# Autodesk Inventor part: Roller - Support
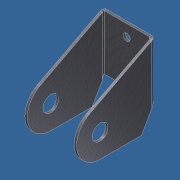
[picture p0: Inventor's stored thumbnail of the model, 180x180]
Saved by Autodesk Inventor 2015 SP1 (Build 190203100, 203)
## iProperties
Category: Mechanical Engineering Drawing and Design - CADD
Manager: Fábio Ricardo de Oliveira Souza
Company: SENAI - Serviço Nacional de Aprendizagem Industrial
Created: 2011-06
Part Number: Roller - Support
Material: Steel
Description: Steel - DIN-20CrMoS4
Document SubType Name: Sheet Metal
Designer: Guilherme Augusto Franco de Souza
Engineer: George Geraldo de Oliveia Silva
Authority: Fábio Ricardo de Oliveira Soza
Density: 7.85 g/cm^3
Flat Pattern Width: 5 cm
Flat Pattern Length: 12.8644 cm
Flat Pattern Area: 64.3221 cm^2
Sheet Metal Rule: Default_mm
Sheet Metal Width: 50,000 mm
Sheet Metal Length: 128,644 mm
Sheet Metal Area: 6432,212 mm^2
Mass: 50.3251 g
Surface Area: 91.6447 cm^2
Volume: 6.41083 cm^3
Appearance: Machined 02
Subject: WorldSkill 2011 - London, England
Author: Guilherme Augusto Franco de Souza
Revision Number: 00
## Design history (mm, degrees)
sketch "Sketch1"
  geometry: L1 (-16.5, -60)-(-16.5, 0); L2 (-16.5, 0)-(16.5, 0); L3 (16.5, 0)-(16.5, -60); 2 further points
  constraints: 6 end point, 2 parallel, 1 coincident, 1 midpoint, 1 perpendicular, 1 vertical
  dimensions: "d0" = 33 distance of L1.end L2.end; "d1" = 60 distance of L1.start L1.end
extrude_surface "ExtrusionSrf1" sketch "Sketch1" dims "d2" = 50, "d3" = 0
sketch "Sketch2"
  geometry: L1 (0, -10)-(-8.66, -25); L2 (0, 25)-(0, -25) reference; L3 (0, 25)-(-41.894, 3.322); L4 (-35, -25)-(-8.66, -25); A1 r 15 centre (-35, -10) between (-41.894, 3.322) and (-35, -25); 2 further points
  constraints: 6 end point, 2 point on circle, 2 tangent, 1 centre point, 1 midpoint, 1 perpendicular, 1 vertical alignment
  dimensions: "d4" = 30 deg angle of L2 L1; "d5" = 10 distance of point (0, 0) L1.start; "d6" = 35 distance from line of L2 A1.centre; "d7" = 25 distance from line of point (0, 0) L4; "d33" = 15 radius of A1
extrude_surface "ExtrusionSrf2" sketch "Sketch2" dims "d9" = 50, "d10" = 0
feature "Trim1"
feature "Trim2"
feature "Trim3"
fillet "Fillet1" dims "d11" = 2
thicken "Thicken1" dims "d12" = 1.5
hole "Hole1" diameter "d15" = 10; stored, may be unused: countersink angle "d19" = 90 deg, drill point angle "d21" = 118 deg; dims "d13" = 10, "d14" = 10, "d16" = 6, "d17" = 4, "d18" = 2, "d20" = 1.5 (= Thickness)
sketch "Sketch3"
  geometry: L1 (0, 0)-(29, 0) reference; L2 (14.5, 27.5)-(14.5, 7.5); 2 further points
  constraints: 2 end point, 1 midpoint, 1 vertical, 1 vertical alignment
  dimensions: "d22" = 20 distance of L2.start L2.end; "d35" = 7.5 distance from line of L1 L2.end
hole "Hole2" sketch "Sketch3" at (14.5, 27.5), (14.5, 7.5) diameter "d26" = 4.5; stored, may be unused: countersink angle "d30" = 90 deg, drill point angle "d32" = 118 deg; dims "d27" = 6, "d28" = 13, "d29" = 3.4, "d31" = 1.5 (= Thickness)
body "Solid1"
body "Srf1"
body "Srf2"
feature "Definition1"
other parameters: "Thickness" = 1.5 (derived), "BendRadius" = 1.5 (= Thickness), "BendReliefWidth" = 1.5 (= Thickness), "BendReliefDepth" = 0.75 (= 0.5 x Thickness), "CornerReliefSize" = 6 (= 4 x Thickness), "SeamGap" = 0.01, "MinimumRemnant" = 3 (= 2 x Thickness), "TransitionRadius" = 1.5 (= BendRadius), "JacobiRadiusSize" = 1.5 (= BendRadius), "GapSize" = 1.5 (= Thickness), "BendRadius" = 1.5, "BendReliefDepth" = 0.75, "BendReliefWidth" = 1.5, "CornerReliefSize" = 6, "GapSize" = 1.5, "JacobiRadiusSize" = 1.5, "MinimumRemnant" = 3, "Thickness" = 1.5, "TransitionRadius" = 1.5
